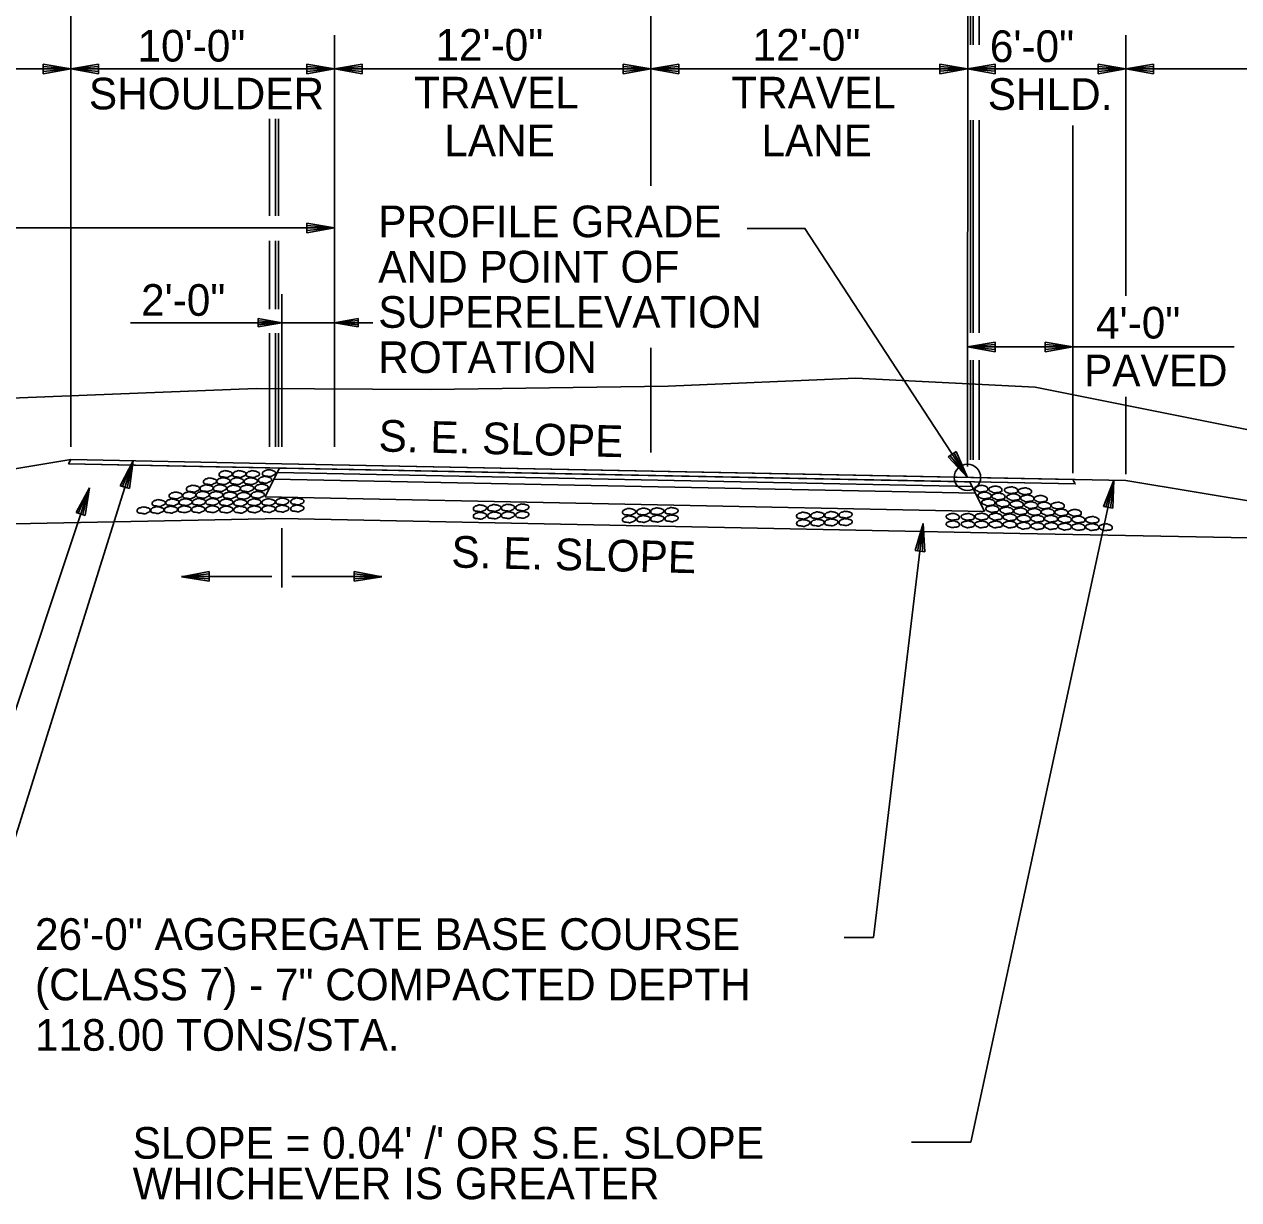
# Model space of a CAD drawing. Extents: x 1734743 to 1735935, y 759845 to 763831.
# Drawn here: x 1735679.6 to 1735725.65, y 763100.4 to 763144.96 of the extents above; entities that cross this region are included whole.
import ezdxf

# ---------------------------------------------------------------- set-up
doc = ezdxf.new("R2010")
doc.units = 0
for name, color, linetype in [('1', 7, 'Continuous'), ('10', 7, 'Continuous'), ('11', 7, 'Continuous'), ('19', 7, 'Continuous'), ('7', 7, 'Continuous'), ('8', 7, 'Continuous'), ('9', 7, 'Continuous'), ('Level 1', 7, 'Continuous'), ('R_Prop Surface', 7, 'Continuous')]:
    doc.layers.add(name, color=color, linetype=linetype)

# ---------------------------------------------------------------- blocks, each defined once
blk = doc.blocks.new('TM')
at = {"layer": '8'}
for p, q in [((-120.309, 21.181), (-119.787, -20.829)), ((0, 0), (-120.309, 21.181)), ((-31.382, 2.945), (-120.176, 10.512)), ((-119.787, -20.829), (0, 0)), ((-119.911, -10.826), (-31.307, -3.057))]:
    blk.add_line(p, q, dxfattribs=at)
blk = doc.blocks.new('ROCKS')
at = {"layer": '1'}
blk.add_spline([(0.013, 0.06), (0.053, 0.053), (0.107, 0.033), (0.133, 0.013), (0.133, -0.007), (0.12, -0.033), (0.107, -0.04), (0.073, -0.053), (0.033, -0.067), (0.013, -0.067), (-0.02, -0.06), (-0.06, -0.053), (-0.087, -0.047), (-0.113, -0.02), (-0.113, -0.007), (-0.107, 0.02), (-0.087, 0.033), (-0.067, 0.047), (-0.033, 0.053), (-0.02, 0.06), (0.013, 0.06)], degree=3, dxfattribs=at)

msp = doc.modelspace()

# ---------------------------------------------------------------- linework, layer by layer
at = {"layer": '11'}
for points in [[(1735627.279, 763130.664), (1735657.463, 763130.861), (1735669.011, 763131.201), (1735672.965, 763130.699), (1735678.446, 763130.759), (1735688.386, 763131.155), (1735695.019, 763131.114), (1735704.012, 763131.236), (1735711.13, 763131.541)], [(1735711.13, 763131.541), (1735717.923, 763131.201), (1735729.812, 763128.821), (1735743.398, 763123.721), (1735757.567, 763120.095)]]:
    msp.add_lwpolyline(points, dxfattribs=at)
at = {"layer": '19'}
for p, q in [((1735681.361, 763138.637), (1735681.361, 763158.388)), ((1735715.361, 763128.196), (1735715.371, 763147.562)), ((1735715.481, 763144.184), (1735715.481, 763146.865)), ((1735715.583, 763144.184), (1735715.583, 763146.865)), ((1735715.81, 763144.184), (1735715.81, 763146.865)), ((1735681.361, 763128.944), (1735681.361, 763144.548)), ((1735691.361, 763128.941), (1735691.361, 763144.548)), ((1735691.361, 763143.265), (1735691.361, 763144.548)), ((1735680.311, 763143.448), (1735680.311, 763143.081)), ((1735681.361, 763143.265), (1735680.311, 763143.448)), ((1735681.081, 763143.291), (1735680.311, 763143.352)), ((1735680.311, 763143.081), (1735681.361, 763143.265)), ((1735680.311, 763143.168), (1735681.081, 763143.238)), ((1735682.411, 763143.448), (1735681.361, 763143.265)), ((1735681.361, 763143.265), (1735682.411, 763143.081)), ((1735682.411, 763143.352), (1735681.641, 763143.291)), ((1735681.641, 763143.238), (1735682.411, 763143.168)), ((1735682.411, 763143.081), (1735682.411, 763143.448)), ((1735690.311, 763143.448), (1735690.311, 763143.081)), ((1735691.361, 763143.265), (1735690.311, 763143.448)), ((1735691.081, 763143.291), (1735690.311, 763143.352)), ((1735690.311, 763143.081), (1735691.361, 763143.265)), ((1735690.311, 763143.168), (1735691.081, 763143.238)), ((1735692.411, 763143.448), (1735691.361, 763143.265)), ((1735691.361, 763143.265), (1735692.411, 763143.081)), ((1735692.411, 763143.352), (1735691.641, 763143.291)), ((1735691.641, 763143.238), (1735692.411, 763143.168)), ((1735692.411, 763143.081), (1735692.411, 763143.448)), ((1735702.311, 763143.448), (1735702.311, 763143.081)), ((1735703.361, 763143.265), (1735702.311, 763143.448)), ((1735703.081, 763143.291), (1735702.311, 763143.352)), ((1735702.311, 763143.081), (1735703.361, 763143.265)), ((1735702.311, 763143.168), (1735703.081, 763143.238)), ((1735704.411, 763143.448), (1735703.361, 763143.265)), ((1735703.361, 763143.265), (1735704.411, 763143.081)), ((1735704.411, 763143.352), (1735703.641, 763143.291)), ((1735703.641, 763143.238), (1735704.411, 763143.168)), ((1735704.411, 763143.081), (1735704.411, 763143.448)), ((1735714.311, 763143.448), (1735714.311, 763143.081)), ((1735715.361, 763143.265), (1735714.311, 763143.448)), ((1735715.081, 763143.291), (1735714.311, 763143.361)), ((1735714.311, 763143.081), (1735715.361, 763143.265)), ((1735714.311, 763143.177), (1735715.081, 763143.238)), ((1735716.411, 763143.448), (1735715.361, 763143.265)), ((1735715.361, 763143.265), (1735716.411, 763143.081)), ((1735716.411, 763143.361), (1735715.641, 763143.291)), ((1735715.641, 763143.238), (1735716.411, 763143.177)), ((1735716.411, 763143.081), (1735716.411, 763143.448)), ((1735720.311, 763143.448), (1735720.311, 763143.081)), ((1735721.361, 763143.265), (1735720.311, 763143.448)), ((1735721.081, 763143.291), (1735720.311, 763143.352)), ((1735720.311, 763143.081), (1735721.361, 763143.265)), ((1735720.311, 763143.168), (1735721.081, 763143.238)), ((1735722.411, 763143.448), (1735721.361, 763143.265)), ((1735721.361, 763143.265), (1735722.411, 763143.081)), ((1735722.411, 763143.352), (1735721.641, 763143.291)), ((1735721.641, 763143.238), (1735722.411, 763143.168)), ((1735722.411, 763143.081), (1735722.411, 763143.448)), ((1735688.897, 763137.69), (1735688.897, 763141.377)), ((1735689.128, 763137.69), (1735689.128, 763141.377)), ((1735689.234, 763137.69), (1735689.234, 763141.377)), ((1735715.481, 763133.266), (1735715.481, 763141.329)), ((1735715.583, 763133.266), (1735715.583, 763141.329)), ((1735715.81, 763133.266), (1735715.81, 763141.329)), ((1735719.358, 763127.936), (1735719.358, 763141.115)), ((1735690.311, 763137.42), (1735690.311, 763137.052)), ((1735691.361, 763137.236), (1735690.311, 763137.42)), ((1735691.081, 763137.262), (1735690.311, 763137.324)), ((1735690.311, 763137.052), (1735691.361, 763137.236)), ((1735690.311, 763137.14), (1735691.081, 763137.21)), ((1735688.897, 763134.156), (1735688.897, 763136.746)), ((1735689.128, 763134.156), (1735689.128, 763136.746)), ((1735689.234, 763134.156), (1735689.234, 763136.746)), ((1735689.361, 763128.941), (1735689.361, 763134.722)), ((1735683.623, 763133.644), (1735692.814, 763133.644)), ((1735688.467, 763133.801), (1735688.467, 763133.488)), ((1735689.361, 763133.644), (1735688.467, 763133.801)), ((1735689.123, 763133.666), (1735688.467, 763133.719)), ((1735688.467, 763133.488), (1735689.361, 763133.644)), ((1735688.467, 763133.562), (1735689.123, 763133.622)), ((1735692.256, 763133.801), (1735691.361, 763133.644)), ((1735691.361, 763133.644), (1735692.256, 763133.487)), ((1735692.256, 763133.726), (1735691.6, 763133.666)), ((1735691.6, 763133.622), (1735692.256, 763133.569)), ((1735692.256, 763133.487), (1735692.256, 763133.801)), ((1735688.897, 763128.941), (1735688.897, 763133.248)), ((1735689.128, 763128.941), (1735689.128, 763133.248)), ((1735689.234, 763128.941), (1735689.234, 763133.248)), ((1735716.411, 763132.912), (1735715.361, 763132.728)), ((1735715.361, 763132.728), (1735725.468, 763132.728)), ((1735715.361, 763132.728), (1735716.411, 763132.544)), ((1735716.411, 763132.815), (1735715.641, 763132.754)), ((1735715.641, 763132.702), (1735716.411, 763132.632)), ((1735716.411, 763132.544), (1735716.411, 763132.912)), ((1735718.308, 763132.912), (1735718.308, 763132.544)), ((1735719.358, 763132.728), (1735718.308, 763132.912)), ((1735719.078, 763132.754), (1735718.308, 763132.816)), ((1735718.308, 763132.544), (1735719.358, 763132.728)), ((1735718.308, 763132.632), (1735719.078, 763132.702)), ((1735715.481, 763128.449), (1735715.481, 763132.226)), ((1735715.583, 763128.449), (1735715.583, 763132.226)), ((1735715.81, 763128.449), (1735715.81, 763132.226)), ((1735721.364, 763128.849), (1735721.364, 763130.82)), ((1735681.361, 763128.461), (1735661.361, 763125.128)), ((1735689.361, 763128.301), (1735681.361, 763128.461)), ((1735714.933, 763128.76), (1735714.63, 763128.557)), ((1735714.63, 763128.557), (1735715.356, 763127.781)), ((1735714.702, 763128.604), (1735715.179, 763127.999)), ((1735715.221, 763128.025), (1735714.859, 763128.704)), ((1735715.356, 763127.781), (1735714.933, 763128.76)), ((1735689.358, 763128.134), (1735681.279, 763128.296)), ((1735683.24, 763127.467), (1735683.725, 763128.414)), ((1735683.323, 763127.442), (1735683.615, 763128.156)), ((1735683.662, 763128.142), (1735683.501, 763127.389)), ((1735683.725, 763128.414), (1735683.588, 763127.356)), ((1735719.448, 763127.532), (1735689.358, 763128.134)), ((1735721.364, 763127.661), (1735689.361, 763128.301)), ((1735689.067, 763127.712), (1735688.73, 763127.038)), ((1735689.193, 763127.964), (1735689.067, 763127.712)), ((1735715.662, 763127.18), (1735689.067, 763127.712)), ((1735689.067, 763127.712), (1735715.662, 763127.18)), ((1735715.662, 763127.18), (1735689.067, 763127.712)), ((1735715.533, 763127.437), (1735689.193, 763127.964)), ((1735715.533, 763127.437), (1735689.193, 763127.964)), ((1735720.915, 763127.67), (1735720.515, 763126.682)), ((1735720.872, 763126.608), (1735720.915, 763127.67)), ((1735721.364, 763127.661), (1735735.568, 763125.294)), ((1735677.526, 763113.75), (1735682.07, 763127.391)), ((1735681.566, 763126.455), (1735682.07, 763127.391)), ((1735681.648, 763126.428), (1735681.955, 763127.135)), ((1735682.002, 763127.12), (1735681.825, 763126.371)), ((1735682.07, 763127.391), (1735681.911, 763126.336)), ((1735683.588, 763127.356), (1735683.24, 763127.467)), ((1735715.662, 763127.18), (1735715.533, 763127.437)), ((1735716.005, 763126.493), (1735715.662, 763127.18)), ((1735720.836, 763127.402), (1735720.606, 763126.667)), ((1735720.788, 763126.627), (1735720.884, 763127.391)), ((1735716.005, 763126.493), (1735688.73, 763127.038)), ((1735688.73, 763127.038), (1735716.005, 763126.493)), ((1735720.515, 763126.682), (1735720.872, 763126.608)), ((1735689.361, 763126.218), (1735664.974, 763125.73)), ((1735681.911, 763126.336), (1735681.566, 763126.455)), ((1735717.349, 763125.658), (1735689.361, 763126.218)), ((1735689.361, 763125.855), (1735689.361, 763123.601)), ((1735713.686, 763126.027), (1735711.799, 763110.335)), ((1735713.38, 763125.009), (1735713.686, 763126.027)), ((1735713.466, 763125), (1735713.625, 763125.754)), ((1735713.674, 763125.749), (1735713.651, 763124.979)), ((1735713.686, 763126.027), (1735713.742, 763124.963)), ((1735735.568, 763125.294), (1735717.349, 763125.658)), ((1735713.742, 763124.963), (1735713.38, 763125.009)), ((1735688.982, 763124.018), (1735685.561, 763124.018)), ((1735689.74, 763124.018), (1735693.161, 763124.018)), ((1735711.799, 763110.335), (1735710.681, 763110.335))]:
    msp.add_line(p, q, dxfattribs=at)
for points in [[(1735719.448, 763127.532), (1735681.279, 763128.296), (1735681.279, 763128.296), (1735681.362, 763128.462), (1735681.362, 763128.462), (1735689.361, 763128.301), (1735717.395, 763127.74), (1735719.359, 763127.701), (1735719.359, 763127.701), (1735719.448, 763127.532), (1735719.448, 763127.532), (1735719.448, 763127.532)], [(1735715.533, 763127.437), (1735689.193, 763127.964), (1735689.193, 763127.964), (1735689.279, 763128.136), (1735689.279, 763128.136), (1735689.379, 763128.134), (1735715.248, 763127.616), (1735715.445, 763127.612), (1735715.445, 763127.612), (1735715.533, 763127.437), (1735715.533, 763127.437), (1735715.533, 763127.437)]]:
    msp.add_lwpolyline(points, dxfattribs=at)
at = {"layer": '7'}
for p, q in [((1735703.361, 763138.837), (1735703.361, 763159.508)), ((1735703.361, 763128.73), (1735703.361, 763132.689))]:
    msp.add_line(p, q, dxfattribs=at)
at = {"layer": '9'}
for p, q in [((1735681.361, 763137.692), (1735681.361, 763144.315)), ((1735721.361, 763134.662), (1735721.361, 763144.548)), ((1735664.974, 763143.265), (1735681.361, 763143.265)), ((1735681.361, 763143.265), (1735691.361, 763143.265)), ((1735691.361, 763143.265), (1735703.361, 763143.265)), ((1735703.361, 763143.265), (1735715.361, 763143.265)), ((1735715.361, 763143.265), (1735721.361, 763143.265)), ((1735721.361, 763143.265), (1735735.568, 763143.264)), ((1735661.361, 763137.236), (1735691.361, 763137.236)), ((1735681.361, 763132.85), (1735681.361, 763136.236)), ((1735681.361, 763129.095), (1735681.361, 763132.85)), ((1735721.361, 763127.9), (1735721.361, 763130.836)), ((1735683.725, 763128.414), (1735676.301, 763104.772)), ((1735720.915, 763127.67), (1735715.487, 763102.583)), ((1735715.487, 763102.583), (1735713.239, 763102.583))]:
    msp.add_line(p, q, dxfattribs=at)
msp.add_lwpolyline([(1735707.006, 763137.218), (1735709.198, 763137.218), (1735715.356, 763127.781)], dxfattribs=at)
msp.add_circle((1735715.361, 763127.781), 0.5, dxfattribs=at)
at = {"layer": 'R_Prop Surface'}
for p, q in [((1735681.361, 763128.461), (1735681.279, 763128.296)), ((1735689.279, 763128.136), (1735688.73, 763127.038)), ((1735689.276, 763128.131), (1735689.193, 763127.964)), ((1735689.063, 763127.705), (1735688.73, 763127.038)), ((1735689.193, 763127.964), (1735689.063, 763127.705)), ((1735715.445, 763127.612), (1735716.005, 763126.493)), ((1735719.359, 763127.701), (1735719.448, 763127.532))]:
    msp.add_line(p, q, dxfattribs=at)

# ---------------------------------------------------------------- block references
at = {"layer": '19', "xscale": 0.008761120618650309}
for p, yscale, rotation in [((1735685.558, 763124.013), -0.008761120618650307, -179.20057588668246), ((1735693.162, 763124.013), 0.008761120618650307, -0.7994241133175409)]:
    msp.add_blockref('TM', p, dxfattribs=dict(at, yscale=yscale, rotation=rotation))
at = {"layer": 'Level 1'}
for p, xscale, yscale, rotation in [((1735687.212, 763127.912), 2.011654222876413, 2.0116542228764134, 2.041282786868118), ((1735687.73, 763127.912), 2.011654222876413, 2.0116542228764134, 2.041282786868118), ((1735688.244, 763127.911), 2.011654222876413, 2.0116542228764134, 2.041282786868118), ((1735688.855, 763127.946), 2.011654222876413, 2.0116542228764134, 2.041282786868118), ((1735686.62, 763127.634), 2.011654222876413, 2.0116542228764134, 2.041282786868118), ((1735687.125, 763127.644), 2.011654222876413, 2.0116542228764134, 2.041282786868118), ((1735687.643, 763127.643), 2.011654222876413, 2.0116542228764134, 2.041282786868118), ((1735688.167, 763127.642), 2.011654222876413, 2.0116542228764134, 2.041282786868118), ((1735688.579, 763127.405), 2.011654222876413, 2.0116542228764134, 2.041282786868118), ((1735688.708, 763127.697), 2.011654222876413, 2.0116542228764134, 2.041282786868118), ((1735685.321, 763127.101), 2.011654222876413, 2.0116542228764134, 2.041282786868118), ((1735685.834, 763127.106), 2.011654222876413, 2.0116542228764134, 2.041282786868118), ((1735685.978, 763127.357), 2.011654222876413, 2.0116542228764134, 2.041282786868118), ((1735686.343, 763127.125), 2.011654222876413, 2.0116542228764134, 2.041282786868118), ((1735686.489, 763127.375), 2.011654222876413, 2.0116542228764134, 2.041282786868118), ((1735686.853, 763127.119), 2.011654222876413, 2.0116542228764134, 2.041282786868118), ((1735686.998, 763127.378), 2.011654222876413, 2.0116542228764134, 2.041282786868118), ((1735687.376, 763127.104), 2.011654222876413, 2.0116542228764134, 2.041282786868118), ((1735687.522, 763127.361), 2.011654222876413, 2.0116542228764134, 2.041282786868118), ((1735687.891, 763127.086), 2.011654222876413, 2.0116542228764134, 2.041282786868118), ((1735688.028, 763127.37), 2.011654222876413, 2.0116542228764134, 2.041282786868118), ((1735688.432, 763127.127), 2.011654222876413, 2.0116542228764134, 2.041282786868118), ((1735715.908, 763127.358), 2.0116542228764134, -2.011654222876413, 177.9586193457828), ((1735716.032, 763127.099), 2.0116542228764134, -2.011654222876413, 177.9586193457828), ((1735716.44, 763127.329), 2.0116542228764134, -2.011654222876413, 177.9586193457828), ((1735716.558, 763127.064), 2.0116542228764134, -2.011654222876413, 177.9586193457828), ((1735717.039, 763127.299), 2.011654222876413, -2.0116542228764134, 177.95871721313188), ((1735717.126, 763127.037), 2.011654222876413, -2.0116542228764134, 177.95871721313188), ((1735717.558, 763127.26), 2.011654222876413, -2.0116542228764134, 177.95871721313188), ((1735717.649, 763126.992), 2.011654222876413, -2.0116542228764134, 177.95871721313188), ((1735718.154, 763126.973), 2.011654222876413, -2.0116542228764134, 177.95871721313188), ((1735684.106, 763126.536), 2.011654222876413, 2.0116542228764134, 2.041282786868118), ((1735684.619, 763126.547), 2.011654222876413, 2.0116542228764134, 2.041282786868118), ((1735684.675, 763126.812), 2.011654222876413, 2.0116542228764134, 2.041282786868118), ((1735685.136, 763126.563), 2.011654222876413, 2.0116542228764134, 2.041282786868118), ((1735685.192, 763126.838), 2.011654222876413, 2.0116542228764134, 2.041282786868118), ((1735685.655, 763126.578), 2.011654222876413, 2.0116542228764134, 2.041282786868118), ((1735685.695, 763126.848), 2.011654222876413, 2.0116542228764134, 2.041282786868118), ((1735686.173, 763126.574), 2.011654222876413, 2.0116542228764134, 2.041282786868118), ((1735686.201, 763126.857), 2.011654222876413, 2.0116542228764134, 2.041282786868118), ((1735686.711, 763126.858), 2.011654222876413, 2.0116542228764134, 2.041282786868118), ((1735686.711, 763126.582), 2.011654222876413, 2.0116542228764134, 2.041282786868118), ((1735687.237, 763126.838), 2.011654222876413, 2.0116542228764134, 2.041282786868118), ((1735687.238, 763126.568), 2.011654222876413, 2.0116542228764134, 2.041282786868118), ((1735687.77, 763126.823), 2.011654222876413, 2.0116542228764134, 2.041282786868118), ((1735687.771, 763126.562), 2.011654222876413, 2.0116542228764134, 2.041282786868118), ((1735688.303, 763126.843), 2.011654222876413, 2.0116542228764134, 2.041282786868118), ((1735688.304, 763126.577), 2.011654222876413, 2.0116542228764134, 2.041282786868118), ((1735688.839, 763126.845), 2.011654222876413, 2.0116542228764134, 2.041282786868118), ((1735688.84, 763126.588), 2.011654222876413, 2.0116542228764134, 2.041282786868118), ((1735689.358, 763126.601), 2.011654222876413, 2.0116542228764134, 2.041282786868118), ((1735689.363, 763126.871), 2.011654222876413, 2.0116542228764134, 2.041282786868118), ((1735689.929, 763126.611), 2.011654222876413, 2.0116542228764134, 2.041282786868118), ((1735689.933, 763126.875), 2.011654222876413, 2.0116542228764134, 2.041282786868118), ((1735696.854, 763126.613), 2.011654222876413, 2.0116542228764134, 3.0987721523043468), ((1735697.397, 763126.625), 2.011654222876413, 2.0116542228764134, 3.0987721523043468), ((1735697.919, 763126.636), 2.011654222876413, 2.0116542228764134, 3.0987721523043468), ((1735698.462, 763126.648), 2.011654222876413, 2.0116542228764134, 3.0987721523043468), ((1735702.511, 763126.478), 2.011654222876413, 2.0116542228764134, 3.0987721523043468), ((1735703.055, 763126.49), 2.011654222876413, 2.0116542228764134, 3.0987721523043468), ((1735703.576, 763126.501), 2.011654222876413, 2.0116542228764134, 3.0987721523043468), ((1735704.119, 763126.513), 2.011654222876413, 2.0116542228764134, 3.0987721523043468), ((1735716.177, 763126.838), 2.0116542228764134, -2.011654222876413, 177.9586193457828), ((1735716.324, 763126.589), 2.0116542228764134, -2.011654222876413, 177.9586193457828), ((1735716.722, 763126.803), 2.0116542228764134, -2.011654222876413, 177.9586193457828), ((1735716.865, 763126.535), 2.0116542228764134, -2.011654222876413, 177.9586193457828), ((1735717.251, 763126.77), 2.0116542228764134, -2.011654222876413, 177.9586193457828), ((1735717.387, 763126.501), 2.0116542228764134, -2.011654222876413, 177.9586193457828), ((1735717.788, 763126.735), 2.011654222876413, -2.0116542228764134, 177.95871721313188), ((1735718.293, 763126.719), 2.011654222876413, -2.0116542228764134, 177.95871721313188), ((1735718.804, 763126.717), 2.011654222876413, -2.0116542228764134, 177.95871721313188), ((1735696.855, 763126.333), 2.011654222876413, 2.0116542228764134, 3.0987721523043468), ((1735697.398, 763126.345), 2.011654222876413, 2.0116542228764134, 3.0987721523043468), ((1735697.92, 763126.356), 2.011654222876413, 2.0116542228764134, 3.0987721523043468), ((1735698.463, 763126.368), 2.011654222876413, 2.0116542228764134, 3.0987721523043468), ((1735702.512, 763126.197), 2.011654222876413, 2.0116542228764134, 3.0987721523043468), ((1735703.056, 763126.21), 2.011654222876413, 2.0116542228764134, 3.0987721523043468), ((1735703.577, 763126.221), 2.011654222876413, 2.0116542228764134, 3.0987721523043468), ((1735704.12, 763126.233), 2.011654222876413, 2.0116542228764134, 3.0987721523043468), ((1735709.11, 763126.336), 2.011654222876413, 2.0116542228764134, 3.0987721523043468), ((1735709.111, 763126.056), 2.011654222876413, 2.0116542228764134, 3.0987721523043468), ((1735709.653, 763126.348), 2.011654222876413, 2.0116542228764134, 3.0987721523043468), ((1735709.654, 763126.068), 2.011654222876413, 2.0116542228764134, 3.0987721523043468), ((1735710.174, 763126.36), 2.011654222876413, 2.0116542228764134, 3.0987721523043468), ((1735710.175, 763126.08), 2.011654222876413, 2.0116542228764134, 3.0987721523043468), ((1735710.717, 763126.372), 2.011654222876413, 2.0116542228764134, 3.0987721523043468), ((1735710.718, 763126.092), 2.011654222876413, 2.0116542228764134, 3.0987721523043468), ((1735714.823, 763126.29), 2.0116542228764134, -2.011654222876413, 177.9586193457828), ((1735715.394, 763126.288), 2.0116542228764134, -2.011654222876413, 177.9586193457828), ((1735715.917, 763126.299), 2.0116542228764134, -2.011654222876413, 177.9586193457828), ((1735716.453, 763126.297), 2.0116542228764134, -2.011654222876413, 177.9586193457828), ((1735716.987, 763126.272), 2.0116542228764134, -2.011654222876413, 177.9586193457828), ((1735717.519, 763126.227), 2.0116542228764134, -2.011654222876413, 177.9586193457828), ((1735717.917, 763126.477), 2.011654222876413, -2.0116542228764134, 177.95871721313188), ((1735718.035, 763126.22), 2.011654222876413, -2.0116542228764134, 177.95871721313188), ((1735718.428, 763126.471), 2.011654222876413, -2.0116542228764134, 177.95871721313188), ((1735718.546, 763126.22), 2.011654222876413, -2.0116542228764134, 177.95871721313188), ((1735718.94, 763126.456), 2.011654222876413, -2.0116542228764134, 177.95871721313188), ((1735719.072, 763126.195), 2.011654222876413, -2.0116542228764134, 177.95871721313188), ((1735719.449, 763126.444), 2.011654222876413, -2.0116542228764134, 177.95871721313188), ((1735719.586, 763126.189), 2.011654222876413, -2.0116542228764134, 177.95871721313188), ((1735720.111, 763126.175), 2.011654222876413, -2.0116542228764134, 177.95871721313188), ((1735714.827, 763126.01), 2.0116542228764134, -2.011654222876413, 177.9586193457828), ((1735715.398, 763126.008), 2.0116542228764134, -2.011654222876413, 177.9586193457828), ((1735715.916, 763126.006), 2.0116542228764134, -2.011654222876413, 177.9586193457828), ((1735716.452, 763126.004), 2.0116542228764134, -2.011654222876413, 177.9586193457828), ((1735716.986, 763126.002), 2.0116542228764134, -2.011654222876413, 177.9586193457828), ((1735717.518, 763125.956), 2.0116542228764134, -2.011654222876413, 177.9586193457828), ((1735718.035, 763125.939), 2.011654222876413, -2.0116542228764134, 177.95871721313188), ((1735718.559, 763125.943), 2.011654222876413, -2.0116542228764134, 177.95871721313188), ((1735719.072, 763125.92), 2.011654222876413, -2.0116542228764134, 177.95871721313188), ((1735719.586, 763125.908), 2.011654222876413, -2.0116542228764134, 177.95871721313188), ((1735720.111, 763125.904), 2.011654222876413, -2.0116542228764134, 177.95871721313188), ((1735720.624, 763125.896), 2.011654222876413, -2.0116542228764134, 177.95871721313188)]:
    msp.add_blockref('ROCKS', p, dxfattribs=dict(at, xscale=xscale, yscale=yscale, rotation=rotation))

# ---------------------------------------------------------------- texts
at = {"layer": '10'}
for s, p in [('10\'-0"', (1735683.893, 763143.544)), ('6\'-0"', (1735716.21, 763143.527)), ('SHOULDER', (1735682.05, 763141.731)), ('SHLD.', (1735716.13, 763141.714)), ('PROFILE GRADE', (1735693.021, 763136.884)), ('AND POINT OF', (1735693.021, 763135.168)), ('2\'-0"', (1735684.028, 763133.906)), ('SUPERELEVATION', (1735693.021, 763133.452)), ('ROTATION  ', (1735693.021, 763131.736))]:
    msp.add_text(s, height=1.2, dxfattribs=at).set_placement(p)
for s, rotation, p in [('S. E. SLOPE', 358.6386, (1735693.024, 763128.765)), ('S. E. SLOPE', 358.6386, (1735695.784, 763124.367)), ("SLOPE = 0.04' /' OR S.E. SLOPE", 360, (1735683.71, 763101.953)), ('WHICHEVER IS GREATER', 360, (1735683.71, 763100.416))]:
    msp.add_text(s, height=1.2, rotation=rotation, dxfattribs=at).set_placement(p)
at = {"layer": '19'}
for s, p in [('12\'-0"', (1735695.19, 763143.58)), ('12\'-0"', (1735707.213, 763143.58)), ('TRAVEL', (1735694.382, 763141.767)), ('TRAVEL', (1735706.405, 763141.767)), ('LANE', (1735695.525, 763139.955)), ('LANE', (1735707.548, 763139.955)), ('4\'-0"', (1735720.236, 763133.045)), ('PAVED', (1735719.782, 763131.232)), ('26\'-0" AGGREGATE BASE COURSE', (1735680.006, 763109.869)), ('(CLASS 7) - 7" COMPACTED DEPTH', (1735680.006, 763107.957)), ('118.00 TONS/STA.', (1735680.006, 763106.045))]:
    msp.add_text(s, height=1.2, dxfattribs=at).set_placement(p)

doc.saveas('drawing.dxf')
